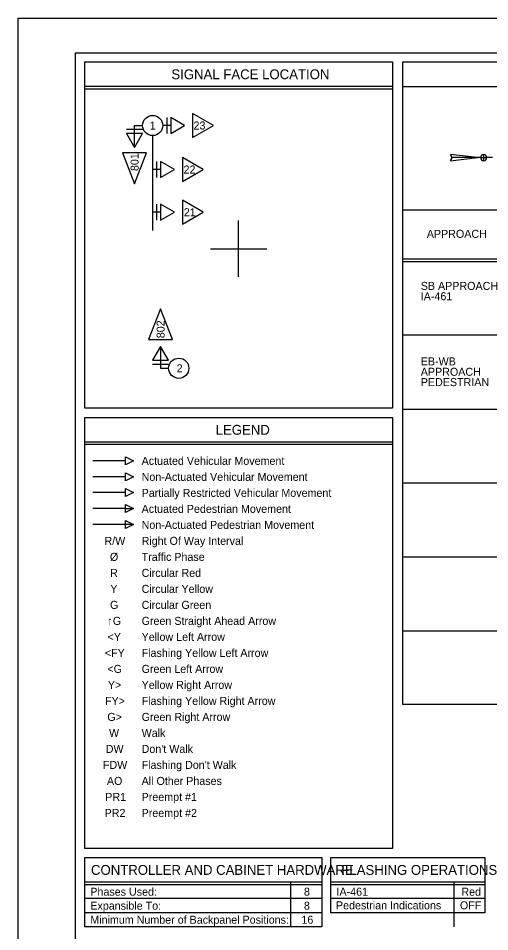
# Model space of a CAD drawing. Extents: x 10040 to 81668, y 7194 to 11018.
# Drawn here: x 10040 to 10806, y 8516 to 10000 of the extents above; entities that cross this region are included whole.
import ezdxf

# ---------------------------------------------------------------- set-up
doc = ezdxf.new("R2010")
doc.units = 0
for name, color, linetype in [('dsnCellElements', 7, 'Continuous'), ('dsnStdTable', 7, 'Continuous'), ('Level 3', 7, 'Continuous'), ('Level 4', 7, 'Continuous'), ('oleRecAreas', 7, 'Continuous'), ('wetSpecialNote', 7, 'Continuous')]:
    doc.layers.add(name, color=color, linetype=linetype)

msp = doc.modelspace()

# ---------------------------------------------------------------- linework, layer by layer
at = {"layer": 'dsnCellElements'}
msp.add_lwpolyline([(10039.6, 10000), (13360.5, 10000), (13360.5, 7806.6), (10039.6, 7806.6)], close=True, dxfattribs=at)
at = {"layer": 'dsnStdTable'}
for p, q in [((10741.9, 9768.6), (10785.9, 9773.6)), ((10795.9, 9773.6), (10795.9, 9778.6)), ((10795.9, 9768.6), (10795.9, 9773.6))]:
    msp.add_line(p, q, dxfattribs=at)
for points in [[(10785.9, 9773.6), (10741.9, 9778.6)], [(10741.9, 9768.6), (10785.9, 9773.6)], [(10785.9, 9773.6), (10743.9, 9773.6)], [(10790.9, 9773.6), (10785.9, 9773.6)], [(10790.9, 9773.6), (10795.9, 9773.6)], [(10795.9, 9773.6), (10800.9, 9773.6)], [(10809.9, 9773.6), (10800.9, 9773.6)]]:
    msp.add_lwpolyline(points, dxfattribs=at)
for centre, radius, start, end in [((10736.7, 9773.6), 7.25, 316.3972, 43.6028), ((10736.7, 9773.6), 7.25, 316.3972, 0), ((10795.9, 9773.6), 5, 360, 180), ((10795.9, 9773.6), 5, 90, 180), ((10795.9, 9773.6), 5, 180, 0), ((10795.9, 9773.6), 5, 270, 360)]:
    msp.add_arc(centre, radius, start, end, dxfattribs=at)
at = {"layer": 'Level 3'}
msp.add_lwpolyline([(10132.5, 9944), (13267.5, 9944), (13267.5, 7924), (10132.5, 7924)], close=True, dxfattribs=at)
msp.add_lwpolyline([(10132.5, 9944), (13267.5, 9944), (13267.5, 7924), (10132.5, 7924)], close=True, dxfattribs=at)
at = {"layer": 'Level 4'}
for p, q in [((10647.5, 9889), (10147.5, 9889)), ((10647.5, 9885), (10147.5, 9885)), ((10664.5, 9889), (12524.5, 9889)), ((10664.5, 9609), (12524.5, 9609)), ((10664.5, 9605), (12524.5, 9605)), ((10647.5, 9311.4), (10147.5, 9311.4)), ((10647.5, 9307.4), (10147.5, 9307.4)), ((10482.5, 8524.2), (10482.5, 8596.4)), ((10747.5, 8524.2), (10747.5, 8596.4)), ((10532.5, 8592.4), (10147.5, 8592.4)), ((10797.5, 8592.4), (10547.5, 8592.4)), ((10532.5, 8569.7), (10147.5, 8569.7)), ((10797.5, 8569.7), (10547.5, 8569.7)), ((10532.5, 8546.9), (10147.5, 8546.9))]:
    msp.add_line(p, q, dxfattribs=at)
for points in [[(10147.5, 9929), (10647.5, 9929), (10647.5, 9366.4), (10147.5, 9366.4)], [(10664.5, 9929), (12524.5, 9929), (12524.5, 8885), (10664.5, 8885)], [(10147.5, 9351.4), (10647.5, 9351.4), (10647.5, 8651.4), (10147.5, 8651.4)], [(10147.5, 8636.4), (10532.5, 8636.4), (10532.5, 8524.2), (10147.5, 8524.2)], [(10547.6, 8636.4), (10797.5, 8636.4), (10797.5, 8546.9), (10547.6, 8546.9)]]:
    msp.add_lwpolyline(points, close=True, dxfattribs=at)
for points in [[(10532.5, 8596.4), (10147.5, 8596.4)], [(10797.5, 8596.4), (10547.5, 8596.4)]]:
    msp.add_lwpolyline(points, dxfattribs=at)
at = {"layer": 'oleRecAreas'}
for p, q in [((10228.5, 9812.8), (10228.5, 9825.8)), ((10228.5, 9825.8), (10241.5, 9825.8)), ((10287.4, 9825.8), (10274.4, 9825.8)), ((10280.9, 9838.8), (10280.9, 9812.8)), ((10241.5, 9819.3), (10215.5, 9819.3)), ((10257.9, 9809.4), (10257.9, 9655.2)), ((10264.4, 9767.3), (10264.4, 9741.3)), ((10270.9, 9754.3), (10257.9, 9754.3)), ((10264.4, 9697.9), (10264.4, 9671.9)), ((10270.9, 9684.9), (10257.9, 9684.9)), ((10270.8, 9444.4), (10270.8, 9431.4)), ((10257.8, 9437.9), (10283.8, 9437.9)), ((10270.8, 9431.4), (10283.8, 9431.4))]:
    msp.add_line(p, q, dxfattribs=at)
for points in [[(10322.9, 9845.3), (10322.9, 9806.3), (10356.6, 9825.8)], [(10287.4, 9838.8), (10287.4, 9812.8), (10309.9, 9825.8)], [(10228.5, 9812.8), (10215.5, 9812.8), (10228.5, 9790.3)], [(10241.5, 9812.8), (10215.5, 9812.8), (10228.5, 9790.3)], [(10248, 9781.2), (10209, 9781.2), (10228.5, 9731.1)], [(10270.9, 9767.3), (10270.9, 9741.3), (10293.4, 9754.3)], [(10306.4, 9773.8), (10306.4, 9734.8), (10340.2, 9754.3)], [(10270.9, 9697.9), (10270.9, 9671.9), (10293.4, 9684.9)], [(10306.4, 9704.4), (10306.4, 9665.4), (10340.2, 9684.9)], [(10251.3, 9478.2), (10290.3, 9478.2), (10270.8, 9528.2)], [(10257.8, 9444.4), (10283.8, 9444.4), (10270.8, 9466.9)], [(10270.8, 9444.4), (10283.8, 9444.4), (10270.8, 9466.9)]]:
    msp.add_lwpolyline(points, close=True, dxfattribs=at)
for centre in [(10257.9, 9825.8), (10300.3, 9431.4)]:
    msp.add_circle(centre, 16.4, dxfattribs=at)
at = {"layer": 'wetSpecialNote'}
for p, q in [((10664.5, 9689), (12524.5, 9689)), ((10397.5, 9625.7), (10397.5, 9671.3)), ((10351.9, 9625.7), (10397.5, 9625.7)), ((10397.5, 9625.7), (10443.2, 9625.7)), ((10397.5, 9580.1), (10397.5, 9625.7)), ((12524.5, 9485), (10664.5, 9485)), ((10664.5, 9365), (12524.5, 9365)), ((10214, 9281), (10160.5, 9281)), ((10214, 9274.5), (10214, 9287.5)), ((10214, 9287.5), (10227, 9281)), ((10214, 9274.5), (10214, 9287.5)), ((10214, 9287.5), (10227, 9281)), ((10227, 9281), (10214, 9274.5)), ((10227, 9281), (10214, 9274.5)), ((10214, 9248.7), (10214, 9261.7)), ((10214, 9261.7), (10227, 9255.2)), ((10214, 9255.2), (10160.5, 9255.2)), ((10227, 9255.2), (10214, 9248.7)), ((10214, 9222.9), (10214, 9235.9)), ((10214, 9235.9), (10227, 9229.4)), ((10214, 9222.9), (10214, 9235.9)), ((10214, 9235.9), (10227, 9229.4)), ((12524.5, 9245), (10664.5, 9245)), ((10214, 9229.4), (10160.5, 9229.4)), ((10227, 9229.4), (10214, 9222.9)), ((10227, 9229.4), (10214, 9222.9)), ((10214, 9203.5), (10160.5, 9203.5)), ((10214, 9210), (10227, 9203.5)), ((10214, 9203.5), (10214, 9210)), ((10214, 9197), (10214, 9203.5)), ((10214, 9203.5), (10227, 9203.5)), ((10227, 9203.5), (10214, 9197)), ((10227, 9177.7), (10160.5, 9177.7)), ((10214, 9171.2), (10214, 9184.2)), ((10214, 9184.2), (10227, 9177.7)), ((10227, 9177.7), (10214, 9171.2)), ((10664.5, 9125), (12524.5, 9125)), ((10664.5, 9005), (12524.5, 9005))]:
    msp.add_line(p, q, dxfattribs=at)

# ---------------------------------------------------------------- texts
at = {"layer": 'dsnStdTable'}
for s, p in [('SB APPROACH', (10693.5, 9558.7)), ('IA-461', (10693.5, 9541.9)), ('EB-WB', (10693.5, 9436.1)), ('APPROACH', (10693.5, 9419.2)), ('PEDESTRIAN', (10693.5, 9402.4))]:
    msp.add_text(s, height=13, dxfattribs=at).set_placement(p)
at = {"layer": 'Level 4'}
for s, height, p in [('SIGNAL FACE LOCATION', 16, (10288.3, 9901)), ('LEGEND', 16, (10360.3, 9323.4)), ('CONTROLLER AND CABINET HARDWARE', 16, (10157.7, 8608.4)), ('FLASHING OPERATIONS', 16, (10564.5, 8608.4)), ('Phases Used:', 13, (10156.6, 8574.5)), ('8', 13, (10503.7, 8574.5)), ('IA-461', 13, (10556.6, 8574.5)), ('Red', 13, (10759.4, 8574.5)), ('Expansible To:', 13, (10156.6, 8551.8)), ('8', 13, (10503.7, 8551.8)), ('Pedestrian Indications', 13, (10555.7, 8552.4)), ('OFF', 13, (10757.1, 8552.4)), ('Minimum Number of Backpanel Positions:', 13, (10156.6, 8529)), ('16', 13, (10499.6, 8529))]:
    msp.add_text(s, height=height, dxfattribs=at).set_placement(p)
at = {"layer": 'oleRecAreas'}
for s, rotation, p in [('1', 360, (10253.2, 9819.3)), ('23', 360, (10324.3, 9819.3)), ('801', 90, (10235, 9751.8)), ('22', 360, (10308.1, 9747.8)), ('21', 360, (10308.5, 9678.4)), ('802', 90, (10277.3, 9480.2)), ('2', 360, (10296.9, 9424.9))]:
    msp.add_text(s, height=13, rotation=rotation, dxfattribs=at).set_placement(p)
at = {"layer": 'wetSpecialNote'}
for s, p in [('APPROACH', (10703.3, 9643.3)), ('Actuated Vehicular Movement', (10240, 9274.5)), ('Non-Actuated Vehicular Movement', (10240, 9248.5)), ('Partially Restricted Vehicular Movement', (10240, 9222.5)), ('Actuated Pedestrian Movement', (10240, 9196.5)), ('Non-Actuated Pedestrian Movement', (10240, 9170.5)), ('R/W', (10179.6, 9144.5)), ('Right Of Way Interval', (10240, 9144.5)), ('Ø', (10188.5, 9118.5)), ('Traffic Phase', (10240, 9118.5)), ('R', (10188.7, 9092.5)), ('Circular Red', (10240, 9092.5)), ('Y', (10189.1, 9066.5)), ('Circular Yellow', (10240, 9066.5)), ('G', (10188.7, 9040.5)), ('Circular Green', (10240, 9040.5)), ('↑', (10184.1, 9014.5)), ('G', (10193.2, 9014.5)), ('Green Straight Ahead Arrow', (10240, 9014.5)), ('<Y', (10184.7, 8988.5)), ('Yellow Left Arrow', (10240, 8988.5)), ('<FY', (10180.2, 8962.5)), ('Flashing Yellow Left Arrow', (10240, 8962.5)), ('<G', (10184.3, 8936.5)), ('Green Left Arrow', (10240, 8936.5)), ('Y>', (10185.1, 8910.5)), ('Yellow Right Arrow', (10240, 8910.5)), ('FY>', (10180.6, 8884.5)), ('Flashing Yellow Right Arrow', (10240, 8884.5)), ('G>', (10184.3, 8858.5)), ('Green Right Arrow', (10240, 8858.5)), ('W', (10187, 8832.5)), ('Walk', (10240, 8832.5)), ('DW', (10181.7, 8806.5)), ("Don't Walk", (10240, 8806.5)), ('FDW', (10177.1, 8780.5)), ("Flashing Don't Walk", (10240, 8780.5)), ('AO', (10183.6, 8754.5)), ('All Other Phases', (10240, 8754.5)), ('PR1', (10180.9, 8728.5)), ('Preempt #1', (10240, 8728.5)), ('PR2', (10179.9, 8702.5)), ('Preempt #2', (10240, 8702.5))]:
    msp.add_text(s, height=13, dxfattribs=at).set_placement(p)

doc.saveas('drawing.dxf')
